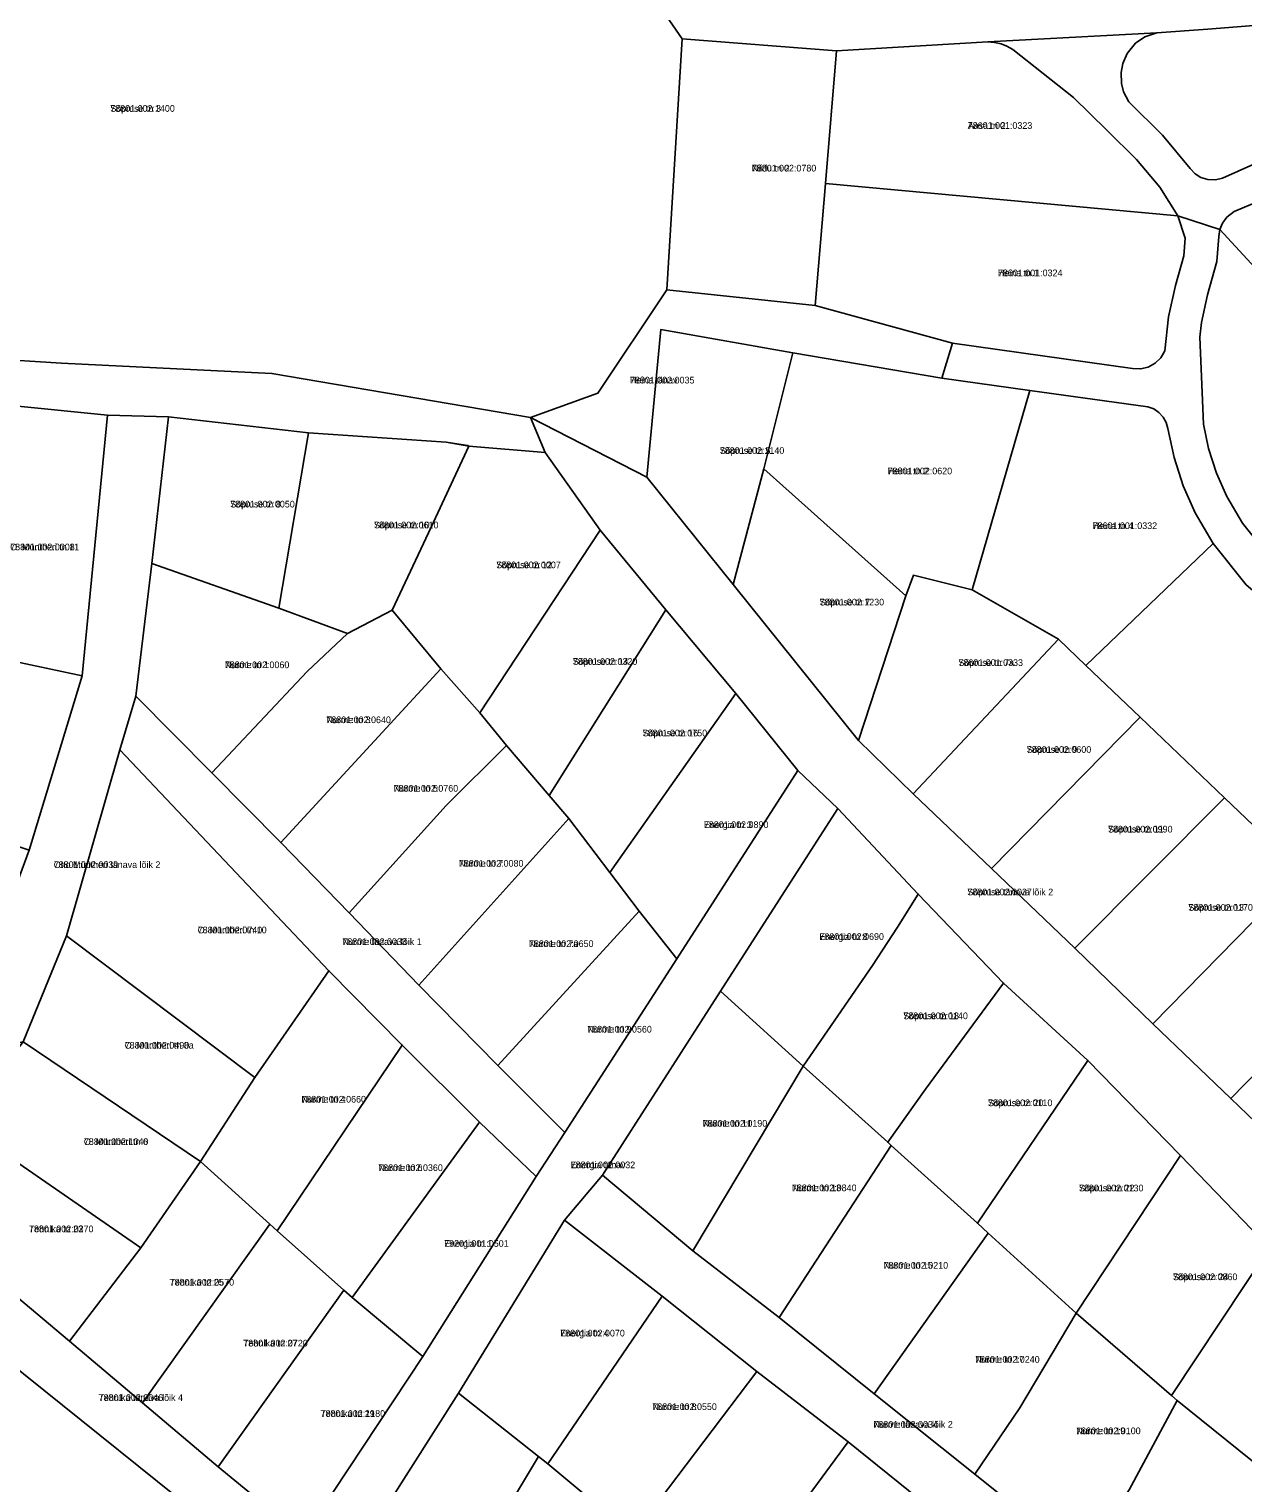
# Model space of a CAD drawing. Extents: x 587616 to 632239, y 6547421 to 6574977.
# Drawn here: x 621060.2 to 621332.9, y 6559884 to 6560210.9 of the extents above; entities that cross this region are included whole.
import ezdxf

# ---------------------------------------------------------------- set-up
doc = ezdxf.new("R2010")
doc.units = 0
for name, color, linetype in [('L_AADRESS', 7, 'Continuous'), ('PIIR', 7, 'Continuous'), ('TUNNUS', 7, 'Continuous')]:
    doc.layers.add(name, color=color, linetype=linetype)

msp = doc.modelspace()

# ---------------------------------------------------------------- linework, layer by layer
at = {"layer": 'PIIR'}
for points in [[(621099, 6560234.38), (621174.53, 6560233.59), (621199.74, 6560219.21), (621206.93, 6560208.72), (621203.52, 6560152.25), (621188, 6560129.02), (621172.9, 6560123.58), (621114.75, 6560133.46), (621067.51, 6560135.74), (621034.33, 6560137.84), (621036.27, 6560159.86), (620988.65, 6560167.89), (620985.4, 6560145.2), (620945.8, 6560157.47), (620961.14, 6560260.98)], [(621206.93, 6560208.72), (621241.63, 6560205.96), (621239.14, 6560176.14), (621236.85, 6560148.74), (621203.52, 6560152.25)], [(621241.63, 6560205.96), (621275.61, 6560208.01), (621277.11, 6560207.89), (621278.66, 6560207.53), (621279.86, 6560207.07), (621281.26, 6560206.3), (621294.9, 6560195.52), (621302.34, 6560188.17), (621309, 6560181.58), (621314.3, 6560175.35), (621318.33, 6560168.89), (621239.14, 6560176.14)], [(621239.14, 6560176.14), (621318.33, 6560168.89), (621319.95, 6560163.86), (621319.69, 6560159.89), (621317.79, 6560153.24), (621316.19, 6560146.18), (621315.37, 6560138.51), (621314.48, 6560136.98), (621313.21, 6560135.74), (621311.66, 6560134.89), (621309.93, 6560134.48), (621308.16, 6560134.54), (621267.67, 6560140.23), (621236.85, 6560148.74)], [(621392.15, 6560127.62), (621372.57, 6560114.56), (621348.82, 6560142.99), (621327.75, 6560165.78), (621328.34, 6560167.26), (621329.32, 6560168.57), (621331.01, 6560169.83), (621335.07, 6560171.6), (621338.6, 6560173.14), (621342.67, 6560174.9), (621346.35, 6560175.56), (621350.08, 6560175.35), (621353.83, 6560174.25), (621355.77, 6560173.25), (621357.72, 6560171.86), (621359.34, 6560170.28), (621360.74, 6560168.48), (621364.47, 6560161.55), (621369.12, 6560154.09), (621374.24, 6560146.92), (621379.79, 6560140.12), (621385.77, 6560133.67)], [(621407.59, 6560074.19), (621402.84, 6560075.14), (621397.51, 6560075.47), (621392.51, 6560075.33), (621387.5, 6560074.59), (621382.98, 6560073.57), (621368.85, 6560075.36), (621358.34, 6560078.58), (621350.81, 6560081.92), (621339.47, 6560091.52), (621332.84, 6560099.8), (621329.33, 6560105.78), (621327.01, 6560111.06), (621325.22, 6560116.58), (621324.06, 6560122.08), (621323.25, 6560141.64), (621323.6, 6560144.93), (621325, 6560151.13), (621327.11, 6560158.61), (621327.51, 6560164.24), (621327.75, 6560165.78), (621348.82, 6560142.99), (621372.57, 6560114.56)], [(620945.8, 6560157.47), (620985.4, 6560145.2), (620992.08, 6560141.9), (621034.33, 6560137.84), (621067.51, 6560135.74), (621114.75, 6560133.46), (621172.9, 6560123.58), (621176.13, 6560115.67), (621159.05, 6560117.13), (621153.89, 6560118.03), (621123.01, 6560120.12), (621091.51, 6560123.67), (621077.81, 6560124.05), (621057.68, 6560126.07), (621035.52, 6560127.15), (621013.05, 6560128.71), (620991.77, 6560130.07), (620974.11, 6560133.78), (620932.68, 6560140.9)], [(621172.9, 6560123.58), (621188, 6560129.02), (621203.52, 6560152.25), (621236.85, 6560148.74), (621267.67, 6560140.23), (621265.31, 6560132.42), (621231.78, 6560138.12), (621202.12, 6560143.31), (621198.99, 6560110.14)], [(621202.12, 6560143.31), (621231.78, 6560138.12), (621225.29, 6560111.97), (621218.43, 6560085.97), (621198.99, 6560110.14)], [(621265.31, 6560132.42), (621285.03, 6560129.62), (621272.09, 6560084.8), (621258.92, 6560088.08), (621257.22, 6560083.42), (621225.29, 6560111.97), (621231.78, 6560138.12)], [(621285.03, 6560129.62), (621311.6, 6560125.97), (621312.91, 6560125.48), (621314.08, 6560124.69), (621315.03, 6560123.66), (621315.71, 6560122.43), (621316.09, 6560121.07), (621317.47, 6560114.53), (621319.52, 6560108.21), (621322.19, 6560102.12), (621326.25, 6560095.25), (621297.68, 6560067.81), (621291.49, 6560073.73), (621272.09, 6560084.8)], [(621057.68, 6560126.07), (621077.81, 6560124.05), (621072.11, 6560065.43), (621034.11, 6560073.56), (621039.13, 6560090.76), (621049.17, 6560088.56)], [(621077.81, 6560124.05), (621091.51, 6560123.67), (621087.79, 6560090.75), (621084.17, 6560060.9), (621080.61, 6560048.81), (621068.61, 6560007.04), (621058.86, 6559983.15), (621039.98, 6559979.54), (621049.6, 6559997.55), (621060.19, 6560026.25), (621072.11, 6560065.43)], [(621123.01, 6560120.12), (621116.34, 6560080.66), (621087.79, 6560090.75), (621091.51, 6560123.67)], [(621172.9, 6560123.58), (621198.99, 6560110.14), (621218.43, 6560085.97), (621246.55, 6560050.95), (621258.82, 6560038.95), (621276.47, 6560022.13), (621295.15, 6560004.21), (621312.68, 6559987.24), (621330.19, 6559970.43), (621348.95, 6559952.47), (621369.13, 6559932.82), (621359.14, 6559917.91), (621338.93, 6559936.88), (621318.9, 6559957.64), (621298.13, 6559978.99), (621279.17, 6559996.39), (621259.98, 6560016.38), (621241.93, 6560035.63), (621232.97, 6560044.15), (621219.04, 6560061.46), (621203.25, 6560080.3), (621188.53, 6560098.22), (621176.13, 6560115.67)], [(621116.34, 6560080.66), (621123.01, 6560120.12), (621153.89, 6560118.03), (621158.79, 6560117.25), (621159.05, 6560117.13), (621150.58, 6560098.92), (621141.82, 6560080.25), (621131.72, 6560075.02)], [(621159.05, 6560117.13), (621176.13, 6560115.67), (621188.53, 6560098.22), (621161.49, 6560057.11), (621152.72, 6560067.05), (621141.82, 6560080.25), (621150.58, 6560098.92)], [(621225.29, 6560111.97), (621257.22, 6560083.42), (621246.55, 6560050.95), (621218.43, 6560085.97)], [(621167.51, 6560049.8), (621161.49, 6560057.11), (621188.53, 6560098.22), (621203.25, 6560080.3), (621177.06, 6560038.56)], [(621328.79, 6560038.03), (621309.89, 6560056.15), (621297.68, 6560067.81), (621326.25, 6560095.25), (621333.7, 6560085.93), (621346.52, 6560075.06), (621355.54, 6560071.07), (621367.17, 6560067.51), (621335.3, 6560031.84)], [(621084.17, 6560060.9), (621087.79, 6560090.75), (621116.34, 6560080.66), (621131.72, 6560075.02), (621122.66, 6560066.45), (621101.28, 6560043.62)], [(621246.55, 6560050.95), (621257.22, 6560083.42), (621258.92, 6560088.08), (621272.09, 6560084.8), (621291.49, 6560073.73), (621258.82, 6560038.95)], [(621101.28, 6560043.62), (621122.66, 6560066.45), (621131.72, 6560075.02), (621141.82, 6560080.25), (621152.72, 6560067.05), (621116.74, 6560027.96)], [(621181.46, 6560033.37), (621177.06, 6560038.56), (621203.25, 6560080.3), (621219.04, 6560061.46), (621190.67, 6560021.24)], [(621034.11, 6560073.56), (621072.11, 6560065.43), (621060.19, 6560026.25), (621011.12, 6560042.49)], [(621258.82, 6560038.95), (621291.49, 6560073.73), (621297.68, 6560067.81), (621309.89, 6560056.15), (621276.47, 6560022.13)], [(621116.74, 6560027.96), (621152.72, 6560067.05), (621161.49, 6560057.11), (621167.51, 6560049.8), (621153.91, 6560036.34), (621132.11, 6560012.21)], [(621084.17, 6560060.9), (621101.28, 6560043.62), (621116.74, 6560027.96), (621132.11, 6560012.21), (621147.8, 6559995.95), (621165.53, 6559977.88), (621180.56, 6559962.8), (621174.14, 6559952.86), (621161.41, 6559965.11), (621144.06, 6559982.44), (621127.58, 6559999.17), (621080.61, 6560048.81)], [(621197.26, 6560012.58), (621190.67, 6560021.24), (621219.04, 6560061.46), (621232.97, 6560044.15), (621205.73, 6560001.81)], [(621276.47, 6560022.13), (621309.89, 6560056.15), (621328.79, 6560038.03), (621295.15, 6560004.21)], [(621080.61, 6560048.81), (621127.58, 6559999.17), (621110.93, 6559975.13), (621068.61, 6560007.04)], [(621153.91, 6560036.34), (621167.51, 6560049.8), (621177.06, 6560038.56), (621181.46, 6560033.37), (621147.8, 6559995.95), (621132.11, 6560012.21)], [(621232.97, 6560044.15), (621241.93, 6560035.63), (621215.58, 6559994.53), (621189.01, 6559953.16), (621180.53, 6559943.05), (621156.66, 6559904.16), (621130.18, 6559862.42), (621121.84, 6559871.88), (621148.71, 6559912.46), (621174.14, 6559952.86), (621180.56, 6559962.8), (621205.73, 6560001.81)], [(621215.58, 6559994.53), (621241.93, 6560035.63), (621259.98, 6560016.38), (621255.35, 6560008.96), (621249.75, 6560000.33), (621234.11, 6559977.71)], [(621295.15, 6560004.21), (621328.79, 6560038.03), (621335.3, 6560031.84), (621346.22, 6560021.46), (621312.68, 6559987.24)], [(621147.8, 6559995.95), (621181.46, 6560033.37), (621190.67, 6560021.24), (621197.26, 6560012.58), (621165.53, 6559977.88)], [(621312.68, 6559987.24), (621346.22, 6560021.46), (621363.58, 6560004.5), (621330.19, 6559970.43)], [(621234.11, 6559977.71), (621249.75, 6560000.33), (621255.35, 6560008.96), (621259.98, 6560016.38), (621279.17, 6559996.39), (621261.64, 6559972.52), (621253.13, 6559960.59)], [(621165.53, 6559977.88), (621197.26, 6560012.58), (621205.73, 6560001.81), (621180.56, 6559962.8)], [(621098.74, 6559956.25), (621058.86, 6559983.15), (621068.61, 6560007.04), (621110.93, 6559975.13)], [(621330.19, 6559970.43), (621363.58, 6560004.5), (621382, 6559986.81), (621348.95, 6559952.47)], [(621110.93, 6559975.13), (621127.58, 6559999.17), (621144.06, 6559982.44), (621115.94, 6559940.69), (621114.27, 6559942.17), (621098.74, 6559956.25)], [(621298.13, 6559978.99), (621273.27, 6559942.37), (621253.89, 6559959.9), (621253.13, 6559960.59), (621261.64, 6559972.52), (621279.17, 6559996.39)], [(621209.34, 6559936.2), (621189.01, 6559953.16), (621215.58, 6559994.53), (621234.11, 6559977.71)], [(621058.86, 6559983.15), (621098.74, 6559956.25), (621085.34, 6559936.83), (621044.75, 6559964.88)], [(621115.94, 6559940.69), (621144.06, 6559982.44), (621161.41, 6559965.11), (621132.79, 6559925.7), (621130.95, 6559927.37)], [(621209.34, 6559936.2), (621234.11, 6559977.71), (621253.13, 6559960.59), (621253.89, 6559959.9), (621228.72, 6559921.19)], [(621275.68, 6559940.17), (621273.27, 6559942.37), (621298.13, 6559978.99), (621318.9, 6559957.64), (621295.47, 6559922.2)], [(621069.28, 6559915.85), (621031.34, 6559947.77), (621044.75, 6559964.88), (621085.34, 6559936.83)], [(621161.41, 6559965.11), (621174.14, 6559952.86), (621148.71, 6559912.46), (621132.79, 6559925.7)], [(621228.72, 6559921.19), (621253.89, 6559959.9), (621273.27, 6559942.37), (621275.68, 6559940.17), (621250.07, 6559904.04)], [(621318.9, 6559957.64), (621338.93, 6559936.88), (621316.89, 6559903.64), (621295.47, 6559922.2)], [(621069.28, 6559915.85), (621085.34, 6559936.83), (621098.74, 6559956.25), (621114.27, 6559942.17), (621085.68, 6559902.02)], [(621189.01, 6559953.16), (621209.34, 6559936.2), (621228.72, 6559921.19), (621250.07, 6559904.04), (621272.74, 6559885.95), (621296.83, 6559866.64), (621319.72, 6559848.57), (621311.92, 6559839.64), (621294.64, 6559853.24), (621280.14, 6559864.72), (621264.38, 6559877), (621244.27, 6559893.25), (621223.72, 6559909.08), (621202.47, 6559926.02), (621180.53, 6559943.05)], [(621031.34, 6559947.77), (621069.28, 6559915.85), (621085.68, 6559902.02), (621102.69, 6559887.65), (621121.84, 6559871.88), (621130.18, 6559862.42), (621119.84, 6559857.1), (621110.44, 6559867.18), (621050.48, 6559915.25), (621022.58, 6559937.22)], [(621102.69, 6559887.65), (621085.68, 6559902.02), (621114.27, 6559942.17), (621115.94, 6559940.69), (621130.95, 6559927.37)], [(621176.76, 6559888.26), (621174.65, 6559889.93), (621156.66, 6559904.16), (621180.53, 6559943.05), (621202.47, 6559926.02)], [(621250.07, 6559904.04), (621275.68, 6559940.17), (621295.47, 6559922.2), (621282.8, 6559900.9), (621272.74, 6559885.95)], [(621318.19, 6559902.52), (621316.89, 6559903.64), (621338.93, 6559936.88), (621359.14, 6559917.91), (621340.1, 6559884.83)], [(621102.69, 6559887.65), (621130.95, 6559927.37), (621132.79, 6559925.7), (621148.71, 6559912.46), (621121.84, 6559871.88)], [(621193.89, 6559874), (621176.76, 6559888.26), (621202.47, 6559926.02), (621223.72, 6559909.08), (621195.92, 6559872.33)], [(621307.39, 6559882.46), (621296.83, 6559866.64), (621272.74, 6559885.95), (621282.8, 6559900.9), (621295.47, 6559922.2), (621316.89, 6559903.64), (621318.19, 6559902.52)], [(621085.15, 6559836.06), (621044.61, 6559870.56), (621027.84, 6559884.83), (621032.85, 6559891.57), (621050.48, 6559915.25), (621110.44, 6559867.18)], [(621212.34, 6559859.3), (621195.92, 6559872.33), (621223.72, 6559909.08), (621244.27, 6559893.25), (621216.71, 6559855.78)], [(621130.18, 6559862.42), (621156.66, 6559904.16), (621174.65, 6559889.93), (621148.95, 6559847.15)], [(621296.83, 6559866.64), (621307.39, 6559882.46), (621318.19, 6559902.52), (621340.1, 6559884.83), (621319.72, 6559848.57)], [(621264.38, 6559877), (621237.22, 6559839.27), (621231.44, 6559843.99), (621216.71, 6559855.78), (621244.27, 6559893.25)], [(621148.95, 6559847.15), (621174.65, 6559889.93), (621176.76, 6559888.26), (621193.89, 6559874), (621167.14, 6559832.49)]]:
    msp.add_lwpolyline(points, close=True, dxfattribs=at)
for points in [[(621414.17, 6560218.09), (621325.07, 6560210.87), (621313.62, 6560210.05), (621275.61, 6560208.01), (621241.63, 6560205.96), (621206.93, 6560208.72), (621199.74, 6560219.21)], [(621335.41, 6560180.48), (621331.87, 6560178.93), (621328.33, 6560177.39), (621326.76, 6560177.01), (621325.07, 6560177.03), (621323.5, 6560177.5), (621322.21, 6560178.31), (621321.08, 6560179.51), (621314.87, 6560187.03), (621307.32, 6560194.49), (621306.13, 6560196.76), (621305.64, 6560198.61), (621305.55, 6560201.09), (621305.95, 6560203.16), (621306.95, 6560205.39), (621308.84, 6560207.68), (621310.94, 6560209.12), (621313.62, 6560210.05), (621325.07, 6560210.87), (621414.17, 6560218.09)], [(621335.07, 6560171.6), (621331.01, 6560169.83), (621329.32, 6560168.57), (621328.34, 6560167.26), (621327.75, 6560165.78), (621318.33, 6560168.89), (621314.3, 6560175.35), (621309, 6560181.58), (621302.34, 6560188.17), (621294.9, 6560195.52), (621281.26, 6560206.3), (621279.86, 6560207.07), (621278.66, 6560207.53), (621277.11, 6560207.89), (621275.61, 6560208.01), (621313.62, 6560210.05), (621310.94, 6560209.12), (621308.84, 6560207.68), (621306.95, 6560205.39), (621305.95, 6560203.16), (621305.55, 6560201.09), (621305.64, 6560198.61), (621306.13, 6560196.76), (621307.32, 6560194.49), (621314.87, 6560187.03), (621321.08, 6560179.51), (621322.21, 6560178.31), (621323.5, 6560177.5), (621325.07, 6560177.03), (621326.76, 6560177.01), (621328.33, 6560177.39), (621331.87, 6560178.93), (621335.41, 6560180.48)], [(621333.7, 6560085.93), (621326.25, 6560095.25), (621322.19, 6560102.12), (621319.52, 6560108.21), (621317.47, 6560114.53), (621316.09, 6560121.07), (621315.71, 6560122.43), (621315.03, 6560123.66), (621314.08, 6560124.69), (621312.91, 6560125.48), (621311.6, 6560125.97), (621285.03, 6560129.62), (621265.31, 6560132.42), (621267.67, 6560140.23), (621308.16, 6560134.54), (621309.93, 6560134.48), (621311.66, 6560134.89), (621313.21, 6560135.74), (621314.48, 6560136.98), (621315.37, 6560138.51), (621316.19, 6560146.18), (621317.79, 6560153.24), (621319.69, 6560159.89), (621319.95, 6560163.86), (621318.33, 6560168.89), (621327.75, 6560165.78), (621327.51, 6560164.24), (621327.11, 6560158.61), (621325, 6560151.13), (621323.6, 6560144.93), (621323.25, 6560141.64), (621324.06, 6560122.08), (621325.22, 6560116.58), (621327.01, 6560111.06), (621329.33, 6560105.78), (621332.84, 6560099.8), (621339.47, 6560091.52)]]:
    msp.add_lwpolyline(points, dxfattribs=at)

# ---------------------------------------------------------------- texts
at = {"layer": 'L_AADRESS'}
for s, p in [('Sõpruse tn 3', (621078.45, 6560192.28)), ('Aasa tn 2', (621271.11, 6560188.45)), ('Niidu tn 2', (621222.58, 6560178.86)), ('Heina tn 1', (621277.89, 6560155.31)), ('Heina tänav', (621195.21, 6560131.2)), ('Sõpruse tn 5', (621215.39, 6560115.37)), ('Heina tn 2', (621253.11, 6560110.77)), ('Sõpruse tn 8', (621105.4, 6560103.32)), ('Sõpruse tn 10', (621137.7, 6560098.62)), ('Heina tn 4', (621299.17, 6560098.46)), ('O. Müntheri tn 11', (621055.96, 6560093.69)), ('Sõpruse tn 12', (621165.18, 6560089.66)), ('Sõpruse tn 7', (621237.82, 6560081.29)), ('Nurme tn 1', (621104.18, 6560067.19)), ('Sõpruse tn 14', (621182.37, 6560067.94)), ('Sõpruse tn 7a', (621269.02, 6560067.69)), ('Nurme tn 3', (621127, 6560054.83)), ('Sõpruse tn 16', (621198.05, 6560051.86)), ('Sõpruse tn 9', (621284.36, 6560048.15)), ('Nurme tn 5', (621142.12, 6560039.42)), ('Energia tn 3', (621211.82, 6560031.25)), ('Sõpruse tn 11', (621302.63, 6560030.24)), ('Otto Müntheri tänava lõik 2', (621065.74, 6560022.26)), ('Nurme tn 7', (621156.79, 6560022.56)), ('Sõpruse tänava lõik 2', (621271.02, 6560016.11)), ('Sõpruse tn 13', (621320.68, 6560012.64)), ('O. Müntheri tn 10', (621098.09, 6560007.57)), ('Nurme tänava lõik 1', (621130.59, 6560004.95)), ('Energia tn 8', (621237.78, 6560006.09)), ('Nurme tn 7a', (621172.53, 6560004.49)), ('Sõpruse tn 18', (621256.64, 6559988.27)), ('Nurme tn 9', (621185.63, 6559985.26)), ('O. Müntheri tn 8a', (621081.69, 6559981.65)), ('Nurme tn 4', (621121.4, 6559969.52)), ('Sõpruse tn 20', (621275.63, 6559968.71)), ('Nurme tn 11', (621211.56, 6559964.1)), ('O. Müntheri tn 6', (621072.51, 6559959.99)), ('Nurme tn 6', (621138.67, 6559954.12)), ('Energia tänav', (621181.89, 6559954.76)), ('Nurme tn 13', (621231.62, 6559949.59)), ('Sõpruse tn 22', (621296.09, 6559949.55)), ('Tehnika tn 23', (621060.18, 6559940.37)), ('Energia tn 1', (621153.46, 6559937.09)), ('Nurme tn 15', (621252.2, 6559932.17)), ('Sõpruse tn 24', (621317.2, 6559929.59)), ('Tehnika tn 25', (621091.78, 6559928.37)), ('Energia tn 4', (621179.56, 6559916.93)), ('Tehnika tn 27', (621108.32, 6559914.68)), ('Nurme tn 17', (621272.77, 6559911.03)), ('Tehnika tänava lõik 4', (621075.83, 6559902.44)), ('Nurme tn 8', (621200.24, 6559900.39)), ('Tehnika tn 29', (621125.7, 6559898.85)), ('Nurme tänava lõik 2', (621249.91, 6559896.4)), ('Nurme tn 19', (621295.46, 6559894.96))]:
    msp.add_text(s, height=1.5, dxfattribs=at).set_placement(p)
at = {"layer": 'TUNNUS'}
for s, p in [('78801:002:1400', (621078.45, 6560192.28)), ('78601:001:0323', (621271.11, 6560188.45)), ('78801:002:0780', (621222.58, 6560178.86)), ('78601:001:0324', (621277.89, 6560155.31)), ('78801:002:0035', (621195.21, 6560131.2)), ('78801:002:1140', (621215.39, 6560115.37)), ('78801:002:0620', (621253.11, 6560110.77)), ('78801:002:0050', (621105.4, 6560103.32)), ('78801:002:0610', (621137.7, 6560098.62)), ('78601:001:0332', (621299.17, 6560098.46)), ('78801:002:0008', (621055.96, 6560093.69)), ('78801:002:0007', (621165.18, 6560089.66)), ('78801:002:1230', (621237.82, 6560081.29)), ('78801:002:0060', (621104.18, 6560067.19)), ('78801:002:0320', (621182.37, 6560067.94)), ('78601:001:0333', (621269.02, 6560067.69)), ('78801:002:0640', (621127, 6560054.83)), ('78801:002:0750', (621198.05, 6560051.86)), ('78801:002:0600', (621284.36, 6560048.15)), ('78801:002:0760', (621142.12, 6560039.42)), ('78801:002:0890', (621211.82, 6560031.25)), ('78801:002:0990', (621302.63, 6560030.24)), ('78801:002:0039', (621065.74, 6560022.26)), ('78801:002:0080', (621156.79, 6560022.56)), ('78801:002:0037', (621271.02, 6560016.11)), ('78801:002:0170', (621320.68, 6560012.64)), ('78801:002:0740', (621098.09, 6560007.57)), ('78801:002:0033', (621130.59, 6560004.95)), ('78801:002:0690', (621237.78, 6560006.09)), ('78801:002:0650', (621172.53, 6560004.49)), ('78801:002:0140', (621256.64, 6559988.27)), ('78801:002:0560', (621185.63, 6559985.26)), ('78801:002:0490', (621081.69, 6559981.65)), ('78801:002:0660', (621121.4, 6559969.52)), ('78801:002:0110', (621275.63, 6559968.71)), ('78801:002:0190', (621211.56, 6559964.1)), ('78801:002:1040', (621072.51, 6559959.99)), ('78801:002:0360', (621138.67, 6559954.12)), ('78801:002:0032', (621181.89, 6559954.76)), ('78801:002:0840', (621231.62, 6559949.59)), ('78801:002:0130', (621296.09, 6559949.55)), ('78801:002:0270', (621060.18, 6559940.37)), ('79201:001:0501', (621153.46, 6559937.09)), ('78801:002:0210', (621252.2, 6559932.17)), ('78801:002:0860', (621317.2, 6559929.59)), ('78801:002:0570', (621091.78, 6559928.37)), ('78801:002:0070', (621179.56, 6559916.93)), ('78801:002:0720', (621108.32, 6559914.68)), ('78801:002:0240', (621272.77, 6559911.03)), ('78801:002:0046', (621075.83, 6559902.44)), ('78801:002:0550', (621200.24, 6559900.39)), ('78801:002:1180', (621125.7, 6559898.85)), ('78801:002:0034', (621249.91, 6559896.4)), ('78801:002:0100', (621295.46, 6559894.96))]:
    msp.add_text(s, height=1.5, dxfattribs=at).set_placement(p)

doc.saveas('drawing.dxf')
